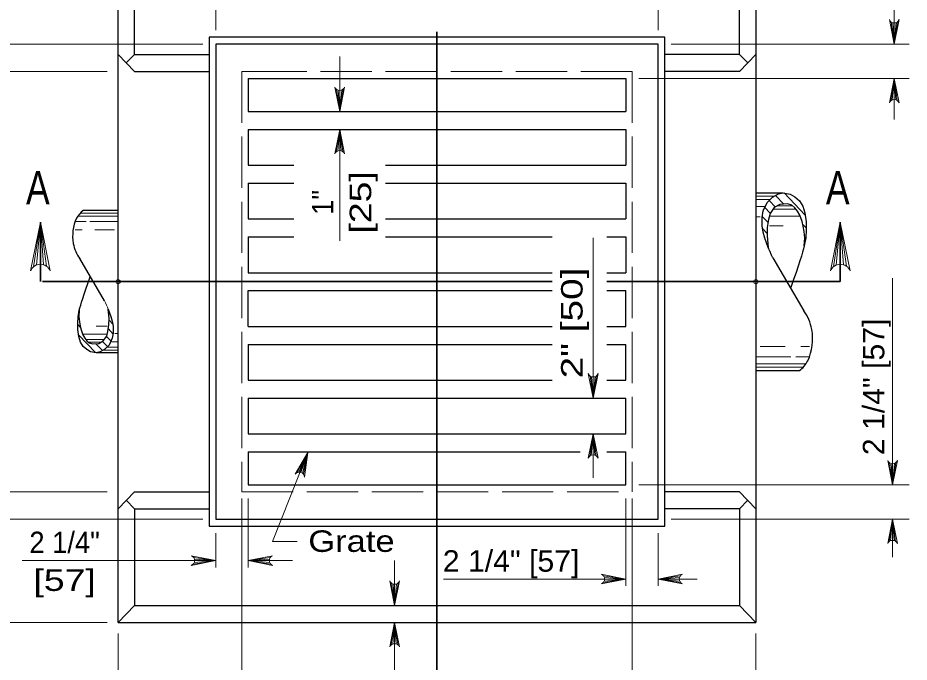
# Model space of a CAD drawing. Extents: x -410.5 to -376.5, y 1617.6 to 1661.6.
# Drawn here: x -395.5 to -389.04, y 1643.13 to 1647.8 of the extents above; entities that cross this region are included whole.
import ezdxf
from ezdxf.enums import TextEntityAlignment as Align

# ---------------------------------------------------------------- set-up
doc = ezdxf.new("R2010")
doc.units = 0
doc.header["$LTSCALE"] = 0.062
doc.header["$PDMODE"] = 32
doc.header["$PDSIZE"] = 0.031
doc.linetypes.add('LONG_DASHED', pattern=[7.5, 6, -1.5])
doc.layers.add('1', color=7, linetype='Continuous', lineweight=13)

msp = doc.modelspace()

# ---------------------------------------------------------------- linework, layer by layer
at = {"layer": '1'}
for p, q in [((-394.06925, 1647.71192), (-394.06925, 1649.99775)), ((-390.85967, 1647.71192), (-390.85967, 1649.99775)), ((-389.148, 1647.61192), (-389.148, 1649.10725)), ((-389.17042, 1647.77217), (-389.148, 1647.61192)), ((-389.15925, 1647.76675), (-389.148, 1647.61192)), ((-389.12317, 1647.77408), (-389.148, 1647.61192)), ((-389.13358, 1647.76792), (-389.148, 1647.61192)), ((-389.148, 1647.76508), (-389.148, 1647.61192)), ((-394.16367, 1647.61192), (-395.76017, 1647.61192)), ((-390.76525, 1647.61192), (-389.03958, 1647.61192)), ((-393.16992, 1647.12225), (-393.16992, 1647.522)), ((-394.85592, 1647.41208), (-396.20775, 1647.41208)), ((-391.00125, 1647.36208), (-389.03958, 1647.36208)), ((-389.17275, 1647.2), (-389.148, 1647.36208)), ((-389.16233, 1647.20608), (-389.148, 1647.36208)), ((-389.148, 1647.36208), (-389.148, 1647.06383)), ((-389.148, 1647.20892), (-389.148, 1647.36208)), ((-389.13667, 1647.20725), (-389.148, 1647.36208)), ((-389.12558, 1647.20183), (-389.148, 1647.36208)), ((-393.19233, 1647.2825), (-393.16992, 1647.12225)), ((-393.18125, 1647.27708), (-393.16992, 1647.12225)), ((-393.14508, 1647.28433), (-393.16992, 1647.12225)), ((-393.1555, 1647.27825), (-393.16992, 1647.12225)), ((-393.16992, 1647.27542), (-393.16992, 1647.12225)), ((-393.19467, 1646.83017), (-393.16992, 1646.99233)), ((-393.18433, 1646.83633), (-393.16992, 1646.99233)), ((-393.16992, 1646.83917), (-393.16992, 1646.99233)), ((-393.15858, 1646.8375), (-393.16992, 1646.99233)), ((-393.1475, 1646.83208), (-393.16992, 1646.99233)), ((-393.16992, 1646.99233), (-393.16992, 1646.18383)), ((-389.94633, 1646.53167), (-389.79333, 1646.36975)), ((-390.15167, 1646.508), (-390.01867, 1646.508)), ((-390.15167, 1646.483), (-390.04942, 1646.483)), ((-390.05517, 1646.47725), (-390.01008, 1646.42958)), ((-390.00908, 1646.51333), (-389.9495, 1646.45025)), ((-390.15167, 1646.43308), (-390.08358, 1646.43308)), ((-390.08683, 1646.42608), (-390.047, 1646.38392)), ((-390.0265, 1646.41292), (-389.85992, 1646.41292)), ((-389.99558, 1646.43792), (-389.88425, 1646.43792)), ((-395.00933, 1646.324), (-395.08858, 1646.324)), ((-394.77725, 1646.364), (-395.06875, 1646.364)), ((-394.77725, 1646.384), (-395.0525, 1646.384)), ((-394.77725, 1646.324), (-394.98117, 1646.324)), ((-390.15167, 1646.35808), (-390.12142, 1646.35808)), ((-390.10508, 1646.36058), (-390.06342, 1646.31642)), ((-390.05375, 1646.36292), (-389.82933, 1646.36292)), ((-395.39008, 1645.99633), (-395.3405, 1646.32058)), ((-395.36933, 1646.00858), (-395.3405, 1646.32058)), ((-395.3405, 1646.01425), (-395.3405, 1646.32058)), ((-395.31783, 1646.011), (-395.3405, 1646.32058)), ((-395.29567, 1646.00008), (-395.3405, 1646.32058)), ((-395.0375, 1646.26408), (-395.08858, 1646.26408)), ((-394.80308, 1646.26408), (-394.94692, 1646.26408)), ((-390.10317, 1646.27383), (-390.06958, 1646.23825)), ((-390.05225, 1646.29217), (-389.95333, 1646.29217)), ((-389.81092, 1646.30342), (-389.78608, 1646.27733)), ((-389.58875, 1645.99633), (-389.53917, 1646.32058)), ((-389.568, 1646.00858), (-389.53917, 1646.32058)), ((-389.53917, 1646.01425), (-389.53917, 1646.32058)), ((-389.5165, 1646.011), (-389.53917, 1646.32058)), ((-389.49433, 1646.00008), (-389.53917, 1646.32058)), ((-391.33167, 1645.04342), (-391.33167, 1646.20592)), ((-389.79725, 1646.20433), (-389.791, 1646.19767)), ((-389.79717, 1646.20175), (-389.79133, 1646.1955)), ((-390.06733, 1646.151), (-390.06308, 1646.1465)), ((-390.0635, 1646.14042), (-390.06242, 1646.13933)), ((-389.799, 1646.16833), (-389.79675, 1646.16592)), ((-389.16, 1644.41383), (-389.16, 1645.91267)), ((-394.84783, 1645.686), (-394.84867, 1645.68692)), ((-394.84475, 1645.6775), (-394.84817, 1645.68117)), ((-395.06075, 1645.63483), (-395.06583, 1645.64017)), ((-395.06083, 1645.63692), (-395.0655, 1645.64192)), ((-395.05933, 1645.66358), (-395.06125, 1645.66558)), ((-395.04992, 1645.55558), (-395.06975, 1645.57642)), ((-394.85683, 1645.56467), (-394.93592, 1645.56467)), ((-394.81608, 1645.57925), (-394.84283, 1645.60767)), ((-394.9415, 1645.373), (-395.06392, 1645.5025)), ((-394.85558, 1645.508), (-395.03517, 1645.508)), ((-394.82908, 1645.45742), (-394.861, 1645.49117)), ((-394.81458, 1645.50983), (-394.84792, 1645.54517)), ((-394.77725, 1645.51183), (-394.8015, 1645.51183)), ((-394.87742, 1645.468), (-395.01067, 1645.468)), ((-394.90208, 1645.448), (-394.99117, 1645.448)), ((-394.89133, 1645.38767), (-394.939, 1645.438)), ((-394.8545, 1645.4165), (-394.8905, 1645.45467)), ((-394.77725, 1645.45183), (-394.83167, 1645.45183)), ((-390.11942, 1645.41783), (-389.93958, 1645.41783)), ((-389.82642, 1645.41783), (-389.76258, 1645.41783)), ((-394.77725, 1645.39192), (-394.88367, 1645.39192)), ((-394.77725, 1645.41192), (-394.85908, 1645.41192)), ((-390.15167, 1645.34283), (-389.89675, 1645.34283)), ((-390.15167, 1645.29283), (-389.78733, 1645.29283)), ((-389.8615, 1645.34283), (-389.76258, 1645.34283)), ((-390.15167, 1645.26792), (-389.80758, 1645.26792)), ((-391.35408, 1645.20367), (-391.33167, 1645.04342)), ((-391.343, 1645.19825), (-391.33167, 1645.04342)), ((-391.30692, 1645.20558), (-391.33167, 1645.04342)), ((-391.31725, 1645.19942), (-391.33167, 1645.04342)), ((-391.33167, 1645.19658), (-391.33167, 1645.04342)), ((-391.35642, 1644.62142), (-391.33167, 1644.78358)), ((-391.34608, 1644.62758), (-391.33167, 1644.78358)), ((-391.33167, 1644.78358), (-391.33167, 1644.46483)), ((-391.33167, 1644.63042), (-391.33167, 1644.78358)), ((-391.32033, 1644.62875), (-391.33167, 1644.78358)), ((-391.30925, 1644.62333), (-391.33167, 1644.78358)), ((-393.47717, 1644.50283), (-393.402, 1644.64867)), ((-393.46533, 1644.50533), (-393.402, 1644.64867)), ((-393.45083, 1644.5035), (-393.402, 1644.64867)), ((-393.44058, 1644.49833), (-393.402, 1644.64867)), ((-393.43183, 1644.48958), (-393.402, 1644.64867)), ((-389.13525, 1644.57592), (-389.16, 1644.41383)), ((-389.18242, 1644.574), (-389.16, 1644.41383)), ((-389.17133, 1644.56858), (-389.16, 1644.41383)), ((-389.14558, 1644.56975), (-389.16, 1644.41383)), ((-389.16, 1644.56692), (-389.16, 1644.41383)), ((-391.00125, 1644.41383), (-389.03958, 1644.41383)), ((-394.85592, 1644.36383), (-396.20775, 1644.36383)), ((-393.8805, 1644.31383), (-393.8805, 1642.69608)), ((-393.83325, 1644.31383), (-393.83325, 1643.81417)), ((-391.09567, 1644.31383), (-391.09567, 1643.68017)), ((-391.0485, 1644.31383), (-391.0485, 1642.69608)), ((-394.16367, 1644.16392), (-395.76017, 1644.16392)), ((-390.76525, 1644.164), (-389.03958, 1644.164)), ((-389.18475, 1644.00192), (-389.16, 1644.164)), ((-389.17442, 1644.008), (-389.16, 1644.164)), ((-389.16, 1644.01083), (-389.16, 1644.164)), ((-389.14867, 1644.00917), (-389.16, 1644.164)), ((-389.13758, 1644.00375), (-389.16, 1644.164)), ((-389.16, 1644.164), (-389.16, 1643.89008)), ((-394.06925, 1644.064), (-394.06925, 1643.81417)), ((-390.85967, 1644.06408), (-390.85967, 1643.68025)), ((-394.2295, 1643.8865), (-394.06925, 1643.86408)), ((-394.22408, 1643.87542), (-394.06925, 1643.86408)), ((-393.673, 1643.8865), (-393.83325, 1643.86408)), ((-393.67842, 1643.87542), (-393.83325, 1643.86408)), ((-394.06925, 1643.86408), (-395.47375, 1643.86408)), ((-394.23142, 1643.83933), (-394.06925, 1643.86408)), ((-394.22525, 1643.84975), (-394.06925, 1643.86408)), ((-394.22242, 1643.86408), (-394.06925, 1643.86408)), ((-393.51167, 1643.86408), (-393.83325, 1643.86408)), ((-393.68008, 1643.86408), (-393.83325, 1643.86408)), ((-393.67725, 1643.84975), (-393.83325, 1643.86408)), ((-393.67117, 1643.83933), (-393.83325, 1643.86408)), ((-392.77125, 1643.53933), (-392.77125, 1643.86392)), ((-391.25592, 1643.75258), (-391.09567, 1643.73017)), ((-391.2505, 1643.74142), (-391.09567, 1643.73017)), ((-390.69942, 1643.75267), (-390.85967, 1643.73025)), ((-390.70483, 1643.7415), (-390.85967, 1643.73025)), ((-392.79367, 1643.6995), (-392.77125, 1643.53933)), ((-392.78258, 1643.69408), (-392.77125, 1643.53933)), ((-392.7465, 1643.70142), (-392.77125, 1643.53933)), ((-392.75683, 1643.69533), (-392.77125, 1643.53933)), ((-392.77125, 1643.6925), (-392.77125, 1643.53933)), ((-391.09567, 1643.73017), (-392.41625, 1643.73017)), ((-391.25783, 1643.70533), (-391.09567, 1643.73017)), ((-391.25167, 1643.71575), (-391.09567, 1643.73017)), ((-391.24883, 1643.73017), (-391.09567, 1643.73017)), ((-390.85967, 1643.73025), (-390.5765, 1643.73025)), ((-390.7065, 1643.73025), (-390.85967, 1643.73025)), ((-390.70367, 1643.71583), (-390.85967, 1643.73025)), ((-390.6975, 1643.70542), (-390.85967, 1643.73025)), ((-394.85592, 1643.41433), (-396.20775, 1643.41433)), ((-392.79608, 1643.25225), (-392.77125, 1643.41433)), ((-392.78567, 1643.25833), (-392.77125, 1643.41433)), ((-392.77125, 1643.41433), (-392.77125, 1642.19508)), ((-392.77125, 1643.26117), (-392.77125, 1643.41433)), ((-392.75992, 1643.25958), (-392.77125, 1643.41433)), ((-392.74883, 1643.25417), (-392.77125, 1643.41433)), ((-394.77725, 1643.33567), (-394.77725, 1642.69608)), ((-390.15167, 1643.33575), (-390.15167, 1642.69608))]:
    msp.add_line(p, q, dxfattribs=at)
at = {"layer": '1', "lineweight": 25}
for p, q in [((-394.65925, 1647.537), (-394.65925, 1648.23658)), ((-390.26983, 1647.537), (-390.26983, 1648.23658)), ((-394.06925, 1647.61192), (-394.06925, 1644.16392)), ((-390.85967, 1647.61192), (-394.06925, 1647.61192)), ((-390.85967, 1644.164), (-390.85967, 1647.61192)), ((-394.65925, 1647.41208), (-394.77725, 1647.537)), ((-394.65925, 1647.537), (-394.71825, 1647.4745)), ((-390.26983, 1647.537), (-390.81258, 1647.537)), ((-390.26983, 1647.41208), (-390.15183, 1647.537)), ((-390.26983, 1647.537), (-390.21083, 1647.4745)), ((-393.83325, 1647.36208), (-393.83325, 1647.12225)), ((-391.09567, 1647.36208), (-391.09567, 1647.12225)), ((-390.26983, 1647.41208), (-390.81258, 1647.41208)), ((-393.83325, 1647.12225), (-391.09567, 1647.12225)), ((-393.83325, 1646.99233), (-391.09567, 1646.99233)), ((-393.83325, 1646.99233), (-393.83325, 1646.73242)), ((-391.09567, 1646.99233), (-391.09567, 1646.73242)), ((-393.83325, 1646.73242), (-393.50292, 1646.73242)), ((-392.83767, 1646.73242), (-391.09567, 1646.73242)), ((-393.83325, 1646.6025), (-393.83325, 1646.34267)), ((-393.83325, 1646.6025), (-393.50292, 1646.6025)), ((-392.83767, 1646.6025), (-391.09567, 1646.6025)), ((-391.09567, 1646.6025), (-391.09567, 1646.34267)), ((-390.15167, 1646.533), (-389.95292, 1646.533)), ((-394.77725, 1646.404), (-395.03008, 1646.404)), ((-393.83325, 1646.34267), (-393.50292, 1646.34267)), ((-392.83767, 1646.34267), (-391.09567, 1646.34267)), ((-393.83325, 1646.21275), (-393.83325, 1645.95292)), ((-393.83325, 1646.21275), (-393.50292, 1646.21275)), ((-392.83767, 1646.21275), (-391.63008, 1646.21275)), ((-391.23208, 1646.21275), (-391.09567, 1646.21275)), ((-391.09567, 1646.21275), (-391.09567, 1645.95292)), ((-394.87625, 1645.74983), (-395.05542, 1646.05633)), ((-390.028, 1646.0605), (-389.804, 1645.67742)), ((-393.83325, 1645.95292), (-391.63008, 1645.95292)), ((-391.23208, 1645.95292), (-391.09567, 1645.95292)), ((-393.83325, 1645.56317), (-393.83325, 1645.823)), ((-393.83325, 1645.823), (-391.63008, 1645.823)), ((-391.23208, 1645.823), (-391.09567, 1645.823)), ((-391.09567, 1645.56317), (-391.09567, 1645.823)), ((-393.83325, 1645.56317), (-391.63008, 1645.56317)), ((-391.23208, 1645.56317), (-391.09567, 1645.56317)), ((-393.83325, 1645.43317), (-393.83325, 1645.17333)), ((-393.83325, 1645.43317), (-391.63008, 1645.43317)), ((-391.23208, 1645.43317), (-391.09567, 1645.43317)), ((-391.09567, 1645.17333), (-391.09567, 1645.43317)), ((-394.77725, 1645.37192), (-394.93633, 1645.37192)), ((-390.15167, 1645.24292), (-389.83567, 1645.24292)), ((-393.83325, 1645.17333), (-391.63008, 1645.17333)), ((-391.23225, 1645.17333), (-391.09567, 1645.17333)), ((-393.83325, 1645.04342), (-391.09567, 1645.04342)), ((-393.83325, 1645.04342), (-393.83325, 1644.78358)), ((-391.09567, 1644.78358), (-391.09567, 1645.04342)), ((-393.83325, 1644.78358), (-391.09567, 1644.78358)), ((-393.83325, 1644.65367), (-393.83325, 1644.41383)), ((-393.83325, 1644.65367), (-391.42617, 1644.65367)), ((-391.23225, 1644.65367), (-391.09567, 1644.65367)), ((-391.09567, 1644.41392), (-391.09567, 1644.65367)), ((-394.65925, 1644.36383), (-394.77725, 1644.23892)), ((-390.26983, 1644.36383), (-390.81258, 1644.36383)), ((-390.26983, 1644.36383), (-390.15183, 1644.23892)), ((-394.65925, 1644.23892), (-394.71825, 1644.30133)), ((-390.26983, 1644.23892), (-390.21083, 1644.30133)), ((-394.65925, 1644.23892), (-394.65925, 1643.53933)), ((-390.26983, 1644.23892), (-390.81258, 1644.23892)), ((-390.26983, 1644.23892), (-390.26983, 1643.53933)), ((-394.06925, 1644.16392), (-390.85967, 1644.164)), ((-394.65925, 1643.53933), (-394.77725, 1643.41433)), ((-394.65925, 1643.53933), (-390.26967, 1643.53942)), ((-390.15167, 1643.41433), (-390.26967, 1643.53942)), ((-394.77725, 1643.41433), (-390.15167, 1643.41442))]:
    msp.add_line(p, q, dxfattribs=at)
at = {"layer": '1', "lineweight": 35}
for p, q in [((-392.4645, 1646.65875), (-392.4645, 1647.70133)), ((-395.3405, 1645.88792), (-395.3405, 1646.32058)), ((-389.53917, 1645.88792), (-389.53917, 1646.32058)), ((-395.32633, 1645.88792), (-391.63008, 1645.88792)), ((-391.23208, 1645.88792), (-389.53917, 1645.88792))]:
    msp.add_line(p, q, dxfattribs=at)
at = {"layer": '1', "linetype": 'LONG_DASHED'}
for p, q in [((-393.8805, 1647.41208), (-393.8805, 1644.36383)), ((-391.0485, 1647.41208), (-391.0485, 1644.36392)), ((-393.8805, 1644.36383), (-391.0485, 1644.36392))]:
    msp.add_line(p, q, dxfattribs=at)
at = {"layer": '1', "lineweight": 25}
for points in [[(-394.77725, 1643.41433), (-394.77725, 1648.3615), (-390.15167, 1648.3615), (-390.15167, 1643.41433)], [(-394.65925, 1647.537), (-394.26292, 1647.537), (-394.1165, 1647.537)], [(-394.65925, 1647.41208), (-394.27933, 1647.41208), (-394.1165, 1647.41208)], [(-393.83325, 1647.36208), (-393.55, 1647.36208), (-391.09567, 1647.36208)], [(-390.06217, 1646.13692), (-390.0865, 1646.203), (-390.09867, 1646.24617), (-390.10633, 1646.29242), (-390.10608, 1646.35433), (-390.09825, 1646.4015), (-390.06983, 1646.46275), (-390.03117, 1646.501), (-389.988, 1646.52508), (-389.95292, 1646.533), (-389.9025, 1646.52333), (-389.86783, 1646.50292), (-389.83575, 1646.475), (-389.81142, 1646.43592), (-389.79542, 1646.3865), (-389.78733, 1646.32242), (-389.78575, 1646.265), (-389.78942, 1646.20617), (-389.80017, 1646.14692)], [(-390.06217, 1646.13692), (-390.0865, 1646.203), (-390.09867, 1646.24617), (-390.10633, 1646.29242), (-390.10608, 1646.35433), (-390.09825, 1646.4015), (-390.06983, 1646.46275), (-390.03117, 1646.501), (-389.988, 1646.52508), (-389.95292, 1646.533), (-389.9025, 1646.52333), (-389.86783, 1646.50292), (-389.83575, 1646.475), (-389.81142, 1646.43592), (-389.79542, 1646.3865), (-389.78733, 1646.32242), (-389.78575, 1646.265), (-389.78942, 1646.20617), (-389.80017, 1646.14692)], [(-389.80017, 1646.14692), (-389.79708, 1646.20275), (-389.80175, 1646.25233), (-389.80725, 1646.29025), (-389.8165, 1646.32425), (-389.83208, 1646.37092), (-389.8495, 1646.39917), (-389.86783, 1646.4235), (-389.88992, 1646.44283), (-389.923, 1646.45258), (-389.97808, 1646.44775), (-390.01758, 1646.42542), (-390.04875, 1646.38167), (-390.05983, 1646.33983), (-390.069, 1646.28058), (-390.06992, 1646.21925), (-390.06217, 1646.13692)], [(-389.80017, 1646.14692), (-389.79708, 1646.20275), (-389.80175, 1646.25233), (-389.80725, 1646.29025), (-389.8165, 1646.32425), (-389.83208, 1646.37092), (-389.8495, 1646.39917), (-389.86783, 1646.4235), (-389.88992, 1646.44283), (-389.923, 1646.45258), (-389.97808, 1646.44775), (-390.01758, 1646.42542), (-390.04875, 1646.38167), (-390.05983, 1646.33983), (-390.069, 1646.28058), (-390.06992, 1646.21925), (-390.06217, 1646.13692)], [(-394.84883, 1645.68883), (-394.82933, 1645.63592), (-394.81967, 1645.60133), (-394.8135, 1645.56442), (-394.81367, 1645.51483), (-394.82, 1645.47708), (-394.84275, 1645.428), (-394.87367, 1645.3975), (-394.90817, 1645.37825), (-394.93633, 1645.37192), (-394.97658, 1645.37967), (-395.00433, 1645.396), (-395.03, 1645.41833), (-395.04942, 1645.44958), (-395.06225, 1645.48908), (-395.06875, 1645.54033), (-395.07008, 1645.58625), (-395.06708, 1645.63333), (-395.05842, 1645.68075)], [(-394.84883, 1645.68883), (-394.82933, 1645.63592), (-394.81967, 1645.60133), (-394.8135, 1645.56442), (-394.81367, 1645.51483), (-394.82, 1645.47708), (-394.84275, 1645.428), (-394.87367, 1645.3975), (-394.90817, 1645.37825), (-394.93633, 1645.37192), (-394.97658, 1645.37967), (-395.00433, 1645.396), (-395.03, 1645.41833), (-395.04942, 1645.44958), (-395.06225, 1645.48908), (-395.06875, 1645.54033), (-395.07008, 1645.58625), (-395.06708, 1645.63333), (-395.05842, 1645.68075)], [(-395.05842, 1645.68075), (-395.06092, 1645.63608), (-395.05717, 1645.59642), (-395.05275, 1645.56617), (-395.04542, 1645.53892), (-395.03292, 1645.50158), (-395.019, 1645.479), (-395.00433, 1645.4595), (-394.98667, 1645.444), (-394.96025, 1645.43617), (-394.91617, 1645.44), (-394.8845, 1645.458), (-394.85958, 1645.493), (-394.85075, 1645.52642), (-394.84342, 1645.57392), (-394.84267, 1645.62292), (-394.84883, 1645.68883)], [(-395.05842, 1645.68075), (-395.06092, 1645.63608), (-395.05717, 1645.59642), (-395.05275, 1645.56617), (-395.04542, 1645.53892), (-395.03292, 1645.50158), (-395.019, 1645.479), (-395.00433, 1645.4595), (-394.98667, 1645.444), (-394.96025, 1645.43617), (-394.91617, 1645.44), (-394.8845, 1645.458), (-394.85958, 1645.493), (-394.85075, 1645.52642), (-394.84342, 1645.57392), (-394.84267, 1645.62292), (-394.84883, 1645.68883)], [(-393.83325, 1644.41383), (-391.39825, 1644.41383), (-391.09567, 1644.41392)], [(-394.65925, 1644.36383), (-394.26108, 1644.36383), (-394.1165, 1644.36383)], [(-394.65925, 1644.23892), (-394.28875, 1644.23892), (-394.1165, 1644.23892)]]:
    msp.add_lwpolyline(points, dxfattribs=at)
at = {"layer": '1'}
for points in [[(-389.11258, 1647.78892), (-389.148, 1647.61192), (-389.18333, 1647.78892)], [(-389.18333, 1647.18508), (-389.148, 1647.36208), (-389.11258, 1647.18508)], [(-393.1345, 1647.29925), (-393.16992, 1647.12225), (-393.20533, 1647.29925)], [(-393.20533, 1646.81533), (-393.16992, 1646.99233), (-393.1345, 1646.81533)], [(-395.41133, 1645.96658), (-395.3405, 1646.32058), (-395.26975, 1645.96658)], [(-389.61, 1645.96658), (-389.53917, 1646.32058), (-389.46833, 1645.96658)], [(-391.29625, 1645.22042), (-391.33167, 1645.04342), (-391.36708, 1645.22042)], [(-391.36708, 1644.60658), (-391.33167, 1644.78358), (-391.29625, 1644.60658)], [(-393.402, 1644.64867), (-393.657, 1644.00233), (-393.47833, 1644.00233)], [(-393.49192, 1644.49217), (-393.402, 1644.64867), (-393.42483, 1644.46958)], [(-389.12458, 1644.59083), (-389.16, 1644.41383), (-389.19542, 1644.59083)], [(-389.19542, 1643.987), (-389.16, 1644.164), (-389.12458, 1643.987)], [(-394.24625, 1643.82875), (-394.06925, 1643.86408), (-394.24625, 1643.8995)], [(-393.65625, 1643.82875), (-393.83325, 1643.86408), (-393.65625, 1643.8995)], [(-391.27267, 1643.69475), (-391.09567, 1643.73017), (-391.27267, 1643.7655)], [(-390.68267, 1643.69483), (-390.85967, 1643.73025), (-390.68267, 1643.76558)], [(-392.73583, 1643.71633), (-392.77125, 1643.53933), (-392.80667, 1643.71633)], [(-392.80667, 1643.23733), (-392.77125, 1643.41433), (-392.73583, 1643.23733)]]:
    msp.add_lwpolyline(points, dxfattribs=at)
at = {"layer": '1', "lineweight": 25}
msp.add_lwpolyline([(-394.1165, 1644.114), (-390.8125, 1644.11408), (-390.8125, 1647.66192), (-394.1165, 1647.66192)], close=True, dxfattribs=at)
at = {"layer": '1', "linetype": 'LONG_DASHED'}
msp.add_lwpolyline([(-391.0485, 1647.41208), (-393.56583, 1647.41208), (-393.8805, 1647.41208)], dxfattribs=at)
at = {"layer": '1', "lineweight": 35}
msp.add_lwpolyline([(-392.4645, 1642.41492), (-392.4645, 1642.7695), (-392.4645, 1646.65875)], dxfattribs=at)
at = {"layer": '1'}
for centre, radius, start, end in [((-389.148, 1647.80324), 0.0382, 202.08782, 337.91395), ((-393.16994, 1647.31353), 0.0382, 202.08782, 337.91395), ((-389.14792, 1647.1708), 0.0382, 22.08782, 157.91395), ((-393.16986, 1646.80101), 0.0382, 22.08782, 157.91395), ((-395.34043, 1645.93802), 0.0764, 22.08782, 157.91395), ((-389.53909, 1645.93802), 0.0764, 22.08782, 157.91395), ((-391.3317, 1645.23472), 0.0382, 202.08782, 337.91395), ((-391.33162, 1644.59228), 0.0382, 22.08782, 157.91395), ((-389.16004, 1644.60509), 0.0382, 202.08782, 337.91395), ((-393.4629, 1644.46731), 0.0382, 3.51634, 139.34247), ((-389.15996, 1643.97272), 0.0382, 22.08782, 157.91395), ((-394.26056, 1643.86415), 0.0382, 292.08605, 67.91218), ((-393.64197, 1643.86415), 0.0382, 112.08782, 247.91395), ((-391.28696, 1643.73017), 0.0382, 292.08605, 67.91218), ((-390.66837, 1643.73025), 0.0382, 112.08782, 247.91395), ((-392.7713, 1643.73059), 0.0382, 202.08782, 337.91395), ((-392.77122, 1643.22307), 0.0382, 22.08782, 157.91395)]:
    msp.add_arc(centre, radius, start, end, dxfattribs=at)
at = {"layer": '1', "lineweight": 25}
for centre, major_axis, start_param, end_param in [((-394.93629, 1646.26148), (0, 0.17367), 0.608535, 1.0523476), ((-394.83509, 1646.21986), (0, 0.28786), 1.1112416, 1.7626188), ((-394.86102, 1646.21537), (0, 0.26008), 1.7657992, 2.2285353), ((-390.04697, 1645.47865), (0, -0.3251), 1.7657992, 2.2285353), ((-390.07938, 1645.47304), (0, -0.35983), 1.1112416, 1.7626188), ((-389.95288, 1645.42102), (0, -0.21709), 0.608535, 1.0523476)]:
    msp.add_ellipse(centre, major_axis=major_axis, ratio=0.944543, start_param=start_param, end_param=end_param, dxfattribs=at)
for points in [[(-390.028, 1646.0605), (-390.04142, 1646.08867), (-390.05267, 1646.11408), (-390.06217, 1646.13692)], [(-389.80017, 1646.14692), (-389.81275, 1646.09542), (-389.83917, 1646.01267), (-389.899, 1645.84458)], [(-395.05842, 1645.68075), (-395.04833, 1645.72192), (-395.02725, 1645.78817), (-394.97942, 1645.92267)]]:
    msp.add_open_spline(points, degree=3, dxfattribs=at)
at = {"layer": '1'}
msp.add_open_spline([(-394.87625, 1645.74983), (-394.86542, 1645.72733), (-394.85642, 1645.70708), (-394.84883, 1645.68883)], degree=3, dxfattribs=at)
for p in [(-394.77725, 1645.88792), (-390.15167, 1645.88792)]:
    msp.add_point(p, dxfattribs=at)

# ---------------------------------------------------------------- texts
for s, height, width, p in [('A', 0.24, 0.8, (-395.359, 1646.44992)), ('A', 0.24, 0.8, (-389.55767, 1646.44992)), ('2 1/4"', 0.156, 0.95, (-395.16504, 1643.918)), ('[57]', 0.156, 1.3, (-395.16504, 1643.644))]:
    msp.add_text(s, height=height, dxfattribs=dict(at, width=width)).set_placement(p, align=Align.CENTER)
for s, width, p in [('[25]', 1.3, (-392.94133, 1646.46321)), ('1"', 0.95, (-393.21533, 1646.46321))]:
    msp.add_text(s, height=0.156, rotation=90, dxfattribs=dict(at, width=width)).set_placement(p, align=Align.CENTER)
for s, width, p in [('2" [50]', 1.35, (-391.40825, 1645.18575)), ('2 1/4" [57]', 1.05, (-389.21967, 1644.629))]:
    msp.add_text(s, height=0.156, rotation=90, dxfattribs=dict(at, width=width)).set_placement(p)
for s, width, p in [('Grate', 1.2, (-393.39758, 1643.92717)), ('2 1/4" [57]', 1.05, (-392.42233, 1643.78325))]:
    msp.add_text(s, height=0.156, dxfattribs=dict(at, width=width)).set_placement(p)

doc.saveas('drawing.dxf')
